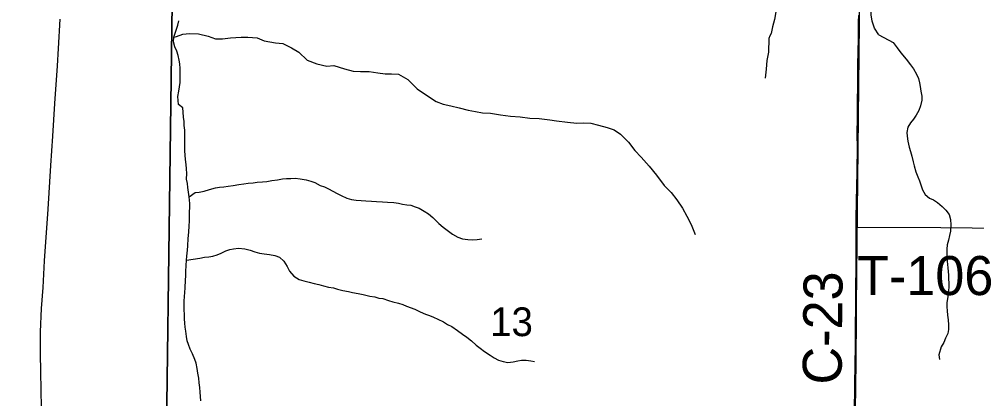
# Model space of a CAD drawing. Extents: x 0 to 34, y 0 to 22.
# Drawn here: x 29.433 to 30.131, y 13.908 to 14.185 of the extents above; entities that cross this region are included whole.
import ezdxf

# ---------------------------------------------------------------- set-up
doc = ezdxf.new("R2010")
doc.units = 0
for name, color, linetype in [('GM_X_County_Road', 7, 'Continuous'), ('GM_X_County_Road_Text', 7, 'Continuous'), ('GM_X_Minor_River', 7, 'Continuous'), ('GM_X_Section', 7, 'Continuous'), ('GM_X_Section_Text', 7, 'Continuous'), ('GM_X_Township_Road', 7, 'Continuous'), ('GM_X_Township_Road_Text', 7, 'Continuous'), ('SC_Scratch1', 7, 'Continuous'), ('SH_Cut_Line', 7, 'Continuous')]:
    doc.layers.add(name, color=color, linetype=linetype)

msp = doc.modelspace()

# ---------------------------------------------------------------- linework, layer by layer
at = {"layer": 'GM_X_County_Road'}
for points in [[(30.0428, 14.03325), (30.04285, 14.03838), (30.04306, 14.0531), (30.04315, 14.0618), (30.04338, 14.07452), (30.0436, 14.09136), (30.04358, 14.10049), (30.04377, 14.11392), (30.04373, 14.12548), (30.04388, 14.1356), (30.04388, 14.14374), (30.04401, 14.15253), (30.04412, 14.15986), (30.04435, 14.17152), (30.0445, 14.18278), (30.04459, 14.18721)], [(30.04159, 13.89971), (30.04185, 13.91691), (30.0421, 13.93519), (30.04218, 13.9448), (30.04237, 13.95822), (30.04233, 13.96437), (30.04239, 13.97205), (30.04256, 13.98233), (30.04271, 14.01081), (30.04278, 14.02281), (30.0428, 14.03129), (30.0428, 14.03325)]]:
    msp.add_lwpolyline(points, dxfattribs=at)
at = {"layer": 'GM_X_Minor_River'}
for points in [[(30.05932, 14.17332), (30.05619, 14.17813), (30.05439, 14.1831), (30.05373, 14.18785), (30.05364, 14.19279), (30.05641, 14.19804), (30.05957, 14.20366), (30.06081, 14.20857), (30.06072, 14.21369), (30.05912, 14.21904), (30.05735, 14.22515), (30.055, 14.23089), (30.05282, 14.23568), (30.05197, 14.24044), (30.05228, 14.24594), (30.05276, 14.25086), (30.05304, 14.2556), (30.05325, 14.26565), (30.05279, 14.27059), (30.05099, 14.27537), (30.04668, 14.28052)], [(29.98428, 14.19006), (29.98316, 14.1844), (29.98186, 14.17912), (29.98077, 14.17422), (29.97977, 14.17254)], [(29.56538, 13.90679), (29.56505, 13.91002), (29.5649, 13.91325), (29.56458, 13.91668), (29.56424, 13.91991), (29.56392, 13.92333), (29.56321, 13.92695), (29.56269, 13.93038), (29.56199, 13.93419), (29.56108, 13.93705), (29.55943, 13.94107), (29.55758, 13.94452), (29.5563, 13.94777), (29.5554, 13.95063), (29.55487, 13.95368), (29.55436, 13.95748), (29.55402, 13.96053), (29.55369, 13.96338), (29.55354, 13.96661), (29.5534, 13.96946), (29.55326, 13.97327), (29.55335, 13.97934), (29.5536, 13.98276), (29.55364, 13.98561), (29.55388, 13.98902), (29.55415, 13.99472), (29.55439, 13.99775), (29.55444, 14.00098), (29.55469, 14.00535), (29.55494, 14.00914), (29.55517, 14.01218), (29.55562, 14.01654), (29.55585, 14.01957), (29.55612, 14.02508), (29.55657, 14.02963), (29.55683, 14.03418), (29.55707, 14.0376), (29.55717, 14.04444), (29.55741, 14.04747), (29.55726, 14.05051), (29.55695, 14.05527), (29.55592, 14.06212), (29.55558, 14.06497), (29.55506, 14.06821), (29.55512, 14.0722), (29.55498, 14.07562), (29.55465, 14.07886), (29.55432, 14.08247), (29.55399, 14.0857), (29.55384, 14.08875), (29.5537, 14.09198), (29.55383, 14.10052), (29.55369, 14.10394), (29.55336, 14.10718), (29.55321, 14.11022), (29.55269, 14.11327), (29.55256, 14.11707), (29.55222, 14.12011), (29.54922, 14.12244), (29.54873, 14.12833), (29.54936, 14.13231), (29.54979, 14.13535), (29.55022, 14.13857), (29.55037, 14.14882), (29.55004, 14.15206), (29.5497, 14.15491), (29.54899, 14.15815), (29.5479, 14.1614), (29.54642, 14.16446), (29.54553, 14.16808), (29.54577, 14.1715), (29.54676, 14.17452), (29.54775, 14.17735), (29.54856, 14.18019), (29.54936, 14.18341)], [(29.54577, 14.1715), (29.54756, 14.1721), (29.55235, 14.17367), (29.55711, 14.17412), (29.56374, 14.17394), (29.57072, 14.17223), (29.57598, 14.17038), (29.5811, 14.17043), (29.587, 14.17103), (29.59479, 14.17157), (29.59954, 14.17164), (29.60635, 14.17107), (29.61142, 14.16885), (29.61973, 14.16748), (29.62521, 14.16695), (29.63139, 14.16374), (29.6368, 14.16056), (29.64291, 14.15488), (29.64985, 14.15204), (29.65721, 14.15051), (29.66234, 14.15094), (29.67005, 14.14845), (29.67646, 14.14676), (29.68157, 14.14643), (29.68803, 14.14663), (29.69427, 14.1457), (29.69955, 14.1448), (29.7043, 14.14486), (29.70941, 14.14454), (29.71614, 14.14074), (29.72297, 14.13391), (29.72987, 14.12936), (29.73676, 14.12461), (29.74183, 14.12276), (29.74749, 14.12166), (29.75352, 14.12017), (29.76012, 14.11847), (29.7654, 14.11738), (29.7705, 14.11648), (29.77637, 14.11632), (29.78374, 14.11498), (29.79092, 14.11402), (29.79792, 14.11345), (29.80511, 14.1125), (29.81174, 14.11232), (29.8195, 14.11135), (29.82441, 14.11065), (29.83235, 14.10967), (29.83916, 14.10892), (29.84429, 14.10916), (29.8494, 14.10883), (29.85506, 14.10754), (29.86147, 14.10584), (29.86635, 14.10419), (29.87119, 14.10083), (29.87692, 14.09517), (29.8815, 14.08916), (29.88611, 14.08409), (29.892, 14.07767), (29.89732, 14.07106), (29.90281, 14.06351), (29.90798, 14.05843), (29.9122, 14.05319), (29.91621, 14.047), (29.91946, 14.04121), (29.92253, 14.03524), (29.92536, 14.02795)], [(29.97977, 14.17254), (29.97916, 14.17046), (29.97889, 14.16059), (29.97759, 14.15455), (29.97723, 14.14829), (29.97648, 14.14166)], [(30.05932, 14.17332), (30.06975, 14.16773), (30.07249, 14.16386), (30.07523, 14.16019), (30.07908, 14.15553), (30.08238, 14.15146), (30.08458, 14.14856), (30.08674, 14.14452), (30.08817, 14.14145), (30.08884, 14.1384), (30.08933, 14.13554), (30.08981, 14.1323), (30.09047, 14.12868), (30.09058, 14.12565), (30.0897, 14.1215), (30.08828, 14.11812), (30.08648, 14.11476), (30.0845, 14.11196), (30.08234, 14.10918), (30.08036, 14.10601), (30.07968, 14.10223), (30.07979, 14.09938), (30.08026, 14.09577), (30.08146, 14.09137), (30.08233, 14.08832), (30.08318, 14.08488), (30.08421, 14.08087), (30.08507, 14.078), (30.08628, 14.07361), (30.0877, 14.06997), (30.08875, 14.0671), (30.08997, 14.06327), (30.09103, 14.0604), (30.09302, 14.05693), (30.09618, 14.05438), (30.09899, 14.05317), (30.10197, 14.0512), (30.1053, 14.04826), (30.10807, 14.04573), (30.11045, 14.04244), (30.11148, 14.03881), (30.11176, 14.03501), (30.11144, 14.03047), (30.11078, 14.02726), (30.10993, 14.02387), (30.10908, 14.02048), (30.1088, 14.01726), (30.10887, 14.01328), (30.10912, 14.00853), (30.10955, 14.00359), (30.10997, 13.99827), (30.11012, 13.98992), (30.11004, 13.98689), (30.10953, 13.98254), (30.10885, 13.97839), (30.10877, 13.97535), (30.10906, 13.97231), (30.10917, 13.96928), (30.10964, 13.96585), (30.11011, 13.96223), (30.11001, 13.95882), (30.10955, 13.95599), (30.10775, 13.95244), (30.10652, 13.94925), (30.10454, 13.94608), (30.10286, 13.94043), (30.10352, 13.937)], [(29.55695, 14.05527), (29.56118, 14.05843), (29.56422, 14.05876), (29.56784, 14.05947), (29.57166, 14.06074), (29.57604, 14.06181), (29.57909, 14.06233), (29.58213, 14.06267), (29.58537, 14.06319), (29.58898, 14.0637), (29.59317, 14.0642), (29.5966, 14.06472), (29.59983, 14.06524), (29.60344, 14.06557), (29.60649, 14.0659), (29.61029, 14.06622), (29.61353, 14.06655), (29.61714, 14.06725), (29.62114, 14.06776), (29.62476, 14.06847), (29.6278, 14.0688), (29.63084, 14.06875), (29.63407, 14.06889), (29.63786, 14.06845), (29.64203, 14.06763), (29.64562, 14.06662), (29.64846, 14.06582), (29.65241, 14.06367), (29.65544, 14.06267), (29.65826, 14.06111), (29.66147, 14.05935), (29.66467, 14.05778), (29.6675, 14.05622), (29.67183, 14.05425), (29.67505, 14.05344), (29.67846, 14.05282), (29.68226, 14.05276), (29.68567, 14.05252), (29.68966, 14.05227), (29.69345, 14.05183), (29.69762, 14.05158), (29.70142, 14.05152), (29.70597, 14.05126), (29.70938, 14.05063), (29.71222, 14.05002), (29.71545, 14.04959), (29.71829, 14.04917), (29.7215, 14.04817), (29.72433, 14.04698), (29.7281, 14.04484), (29.73111, 14.04308), (29.73449, 14.04037), (29.73879, 14.03593), (29.74198, 14.03322), (29.74574, 14.03032), (29.74874, 14.02818), (29.75251, 14.02603), (29.7561, 14.02484), (29.75989, 14.0244), (29.76312, 14.02416), (29.76673, 14.02429), (29.76996, 14.02481)], [(29.55494, 14.00914), (29.56465, 14.0107), (29.56808, 14.01141), (29.57112, 14.01174), (29.57417, 14.01226), (29.57722, 14.01316), (29.58008, 14.01445), (29.58353, 14.01592), (29.58639, 14.01701), (29.58925, 14.01754), (29.59286, 14.01805), (29.59741, 14.01741), (29.6012, 14.01659), (29.60479, 14.01521), (29.60819, 14.0144), (29.6116, 14.01396), (29.61539, 14.01334), (29.61937, 14.0127), (29.62277, 14.01132), (29.62596, 14.00861), (29.62837, 14.00459), (29.63003, 14.00133), (29.63301, 13.99768), (29.63696, 13.99515), (29.64037, 13.99415), (29.64434, 13.99332), (29.64793, 13.99232), (29.65134, 13.99151), (29.65474, 13.9905), (29.65834, 13.98969), (29.66194, 13.98906), (29.66496, 13.98807), (29.66875, 13.98706), (29.67292, 13.98642), (29.67594, 13.98581), (29.67992, 13.98499), (29.68352, 13.98417), (29.68844, 13.98315), (29.69223, 13.98252), (29.69506, 13.98171), (29.69791, 13.98129), (29.70206, 13.9799), (29.70528, 13.9789), (29.70944, 13.97788), (29.71246, 13.97688), (29.7153, 13.97589), (29.72134, 13.97352), (29.72511, 13.97175), (29.72907, 13.96998), (29.73191, 13.96899), (29.73493, 13.9678), (29.73795, 13.96642), (29.7421, 13.96446), (29.74511, 13.96252), (29.74831, 13.96095), (29.75226, 13.95804), (29.75601, 13.95532), (29.75921, 13.95318), (29.76259, 13.95047), (29.76596, 13.94738), (29.76897, 13.94524), (29.77197, 13.94273), (29.77611, 13.94019), (29.77912, 13.93825), (29.78232, 13.93649), (29.78554, 13.93549), (29.78894, 13.93468), (29.79294, 13.93518), (29.79618, 13.93589), (29.79903, 13.93642), (29.80245, 13.93637), (29.80567, 13.93594), (29.80852, 13.93551)]]:
    msp.add_lwpolyline(points, dxfattribs=at)
at = {"layer": 'GM_X_Section'}
for points in [[(29.03576, 14.24326), (29.54494, 14.23257), (29.53789, 13.70397), (29.02875, 13.69082)], [(30.04003, 13.72439), (29.53789, 13.70397), (29.54494, 14.23257), (30.04529, 14.22791)]]:
    msp.add_lwpolyline(points, close=True, dxfattribs=at)
at = {"layer": 'GM_X_Township_Road'}
for points in [[(29.44933, 13.90182), (29.44884, 13.9279), (29.44866, 13.94125), (29.44861, 13.95708), (29.44942, 13.97414), (29.45043, 13.98932), (29.45163, 14.0088), (29.4542, 14.04647), (29.45613, 14.0781), (29.45763, 14.09947), (29.4591, 14.12334), (29.46098, 14.1506), (29.4618, 14.16331), (29.46297, 14.18471)], [(30.0428, 14.03325), (30.10435, 14.03303), (30.33355, 14.03049)]]:
    msp.add_lwpolyline(points, dxfattribs=at)
at = {"layer": 'SC_Scratch1'}
for points in [[(30.04501, 14.18759), (30.04493, 14.18311), (30.04473, 14.1719), (30.04453, 14.16017), (30.0444, 14.15276), (30.04435, 14.14405), (30.04431, 14.13582), (30.04426, 14.12586), (30.04414, 14.11426), (30.04401, 14.10089), (30.04392, 14.0917), (30.04373, 14.07476), (30.0436, 14.06206), (30.04345, 14.05345), (30.0432, 14.03868), (30.04317, 14.03356), (30.04316, 14.03161), (30.0431, 14.02309), (30.04303, 14.01111), (30.04283, 13.98263), (30.04276, 13.97228), (30.04271, 13.96468), (30.04267, 13.95848), (30.04248, 13.94525), (30.04242, 13.93548), (30.04223, 13.91705), (30.04192, 13.89997)], [(30.04192, 13.89997), (30.04223, 13.91705), (30.04242, 13.93548), (30.04248, 13.94525), (30.04267, 13.95848), (30.04271, 13.96468), (30.04276, 13.97228), (30.04283, 13.98263), (30.04303, 14.01111), (30.0431, 14.02309), (30.04316, 14.03161), (30.04317, 14.03356), (30.0432, 14.03868), (30.04345, 14.05345), (30.0436, 14.06206), (30.04373, 14.07476), (30.04392, 14.0917), (30.04401, 14.10089), (30.04414, 14.11426), (30.04426, 14.12586), (30.04431, 14.13582), (30.04435, 14.14405), (30.0444, 14.15276), (30.04453, 14.16017), (30.04473, 14.1719), (30.04493, 14.18311), (30.04501, 14.18759)]]:
    msp.add_lwpolyline(points, dxfattribs=at)
at = {"layer": 'SH_Cut_Line'}
for points in [[(30.04501, 14.18759), (30.04493, 14.18311), (30.04473, 14.1719), (30.04453, 14.16017), (30.0444, 14.15276), (30.04435, 14.14405), (30.04431, 14.13582), (30.04426, 14.12586), (30.04414, 14.11426), (30.04401, 14.10089), (30.04392, 14.0917), (30.04373, 14.07476), (30.0436, 14.06206), (30.04345, 14.05345), (30.0432, 14.03868), (30.04317, 14.03356), (30.04316, 14.03161), (30.0431, 14.02309), (30.04303, 14.01111), (30.04283, 13.98263), (30.04276, 13.97228), (30.04271, 13.96468), (30.04267, 13.95848), (30.04248, 13.94525), (30.04242, 13.93548), (30.04223, 13.91705), (30.04192, 13.89997)], [(30.04192, 13.89997), (30.04223, 13.91705), (30.04242, 13.93548), (30.04248, 13.94525), (30.04267, 13.95848), (30.04271, 13.96468), (30.04276, 13.97228), (30.04283, 13.98263), (30.04303, 14.01111), (30.0431, 14.02309), (30.04316, 14.03161), (30.04317, 14.03356), (30.0432, 14.03868), (30.04345, 14.05345), (30.0436, 14.06206), (30.04373, 14.07476), (30.04392, 14.0917), (30.04401, 14.10089), (30.04414, 14.11426), (30.04426, 14.12586), (30.04431, 14.13582), (30.04435, 14.14405), (30.0444, 14.15276), (30.04453, 14.16017), (30.04473, 14.1719), (30.04493, 14.18311), (30.04501, 14.18759)]]:
    msp.add_lwpolyline(points, dxfattribs=at)

# ---------------------------------------------------------------- texts
at = {"layer": 'GM_X_County_Road_Text'}
msp.add_text('C-23', height=0.028409, rotation=89.47012, dxfattribs=at).set_placement((30.03212, 13.91861))
at = {"layer": 'GM_X_Section_Text'}
msp.add_text('13', height=0.020928, rotation=0.00001, dxfattribs=at).set_placement((29.77612, 13.95395))
at = {"layer": 'GM_X_Township_Road_Text'}
msp.add_text('T-106', height=0.028409, rotation=0.00001, dxfattribs=at).set_placement((30.04341, 13.98383))

doc.saveas('drawing.dxf')
